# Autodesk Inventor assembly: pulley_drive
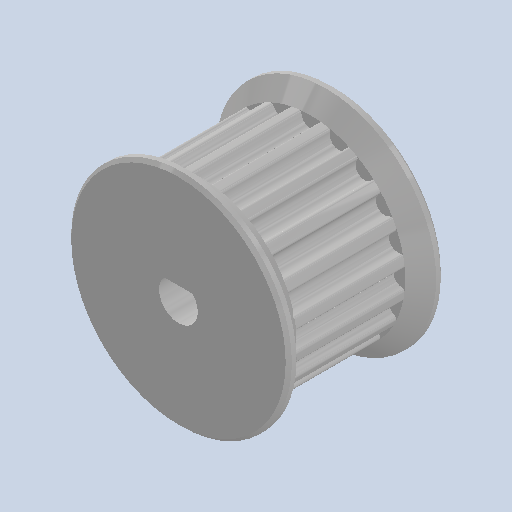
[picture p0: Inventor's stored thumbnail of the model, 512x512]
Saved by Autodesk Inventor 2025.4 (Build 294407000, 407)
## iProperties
Created: 2026-05
Part Number: pulley_drive
Document SubType Name: Assembly
Designer: AdminForWorker
Title: pulley_drive v1
Author: AdminForWorker
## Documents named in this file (2)
- c:\worker\convert-fusion-r03-cosv3\tmp\job-1\47\temp\files\a049fa3f-5bf1-466f-bf17-ec971191c5be\554b67df-005f-4de3-a7de-0a2898899102.iam
- c:\worker\convert-fusion-r03-cosv3\tmp\job-1\47\temp\files\a049fa3f-5bf1-466f-bf17-ec971191c5be\Component1.ipt
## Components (1 placed, 1 different names)
1. Component1:1
